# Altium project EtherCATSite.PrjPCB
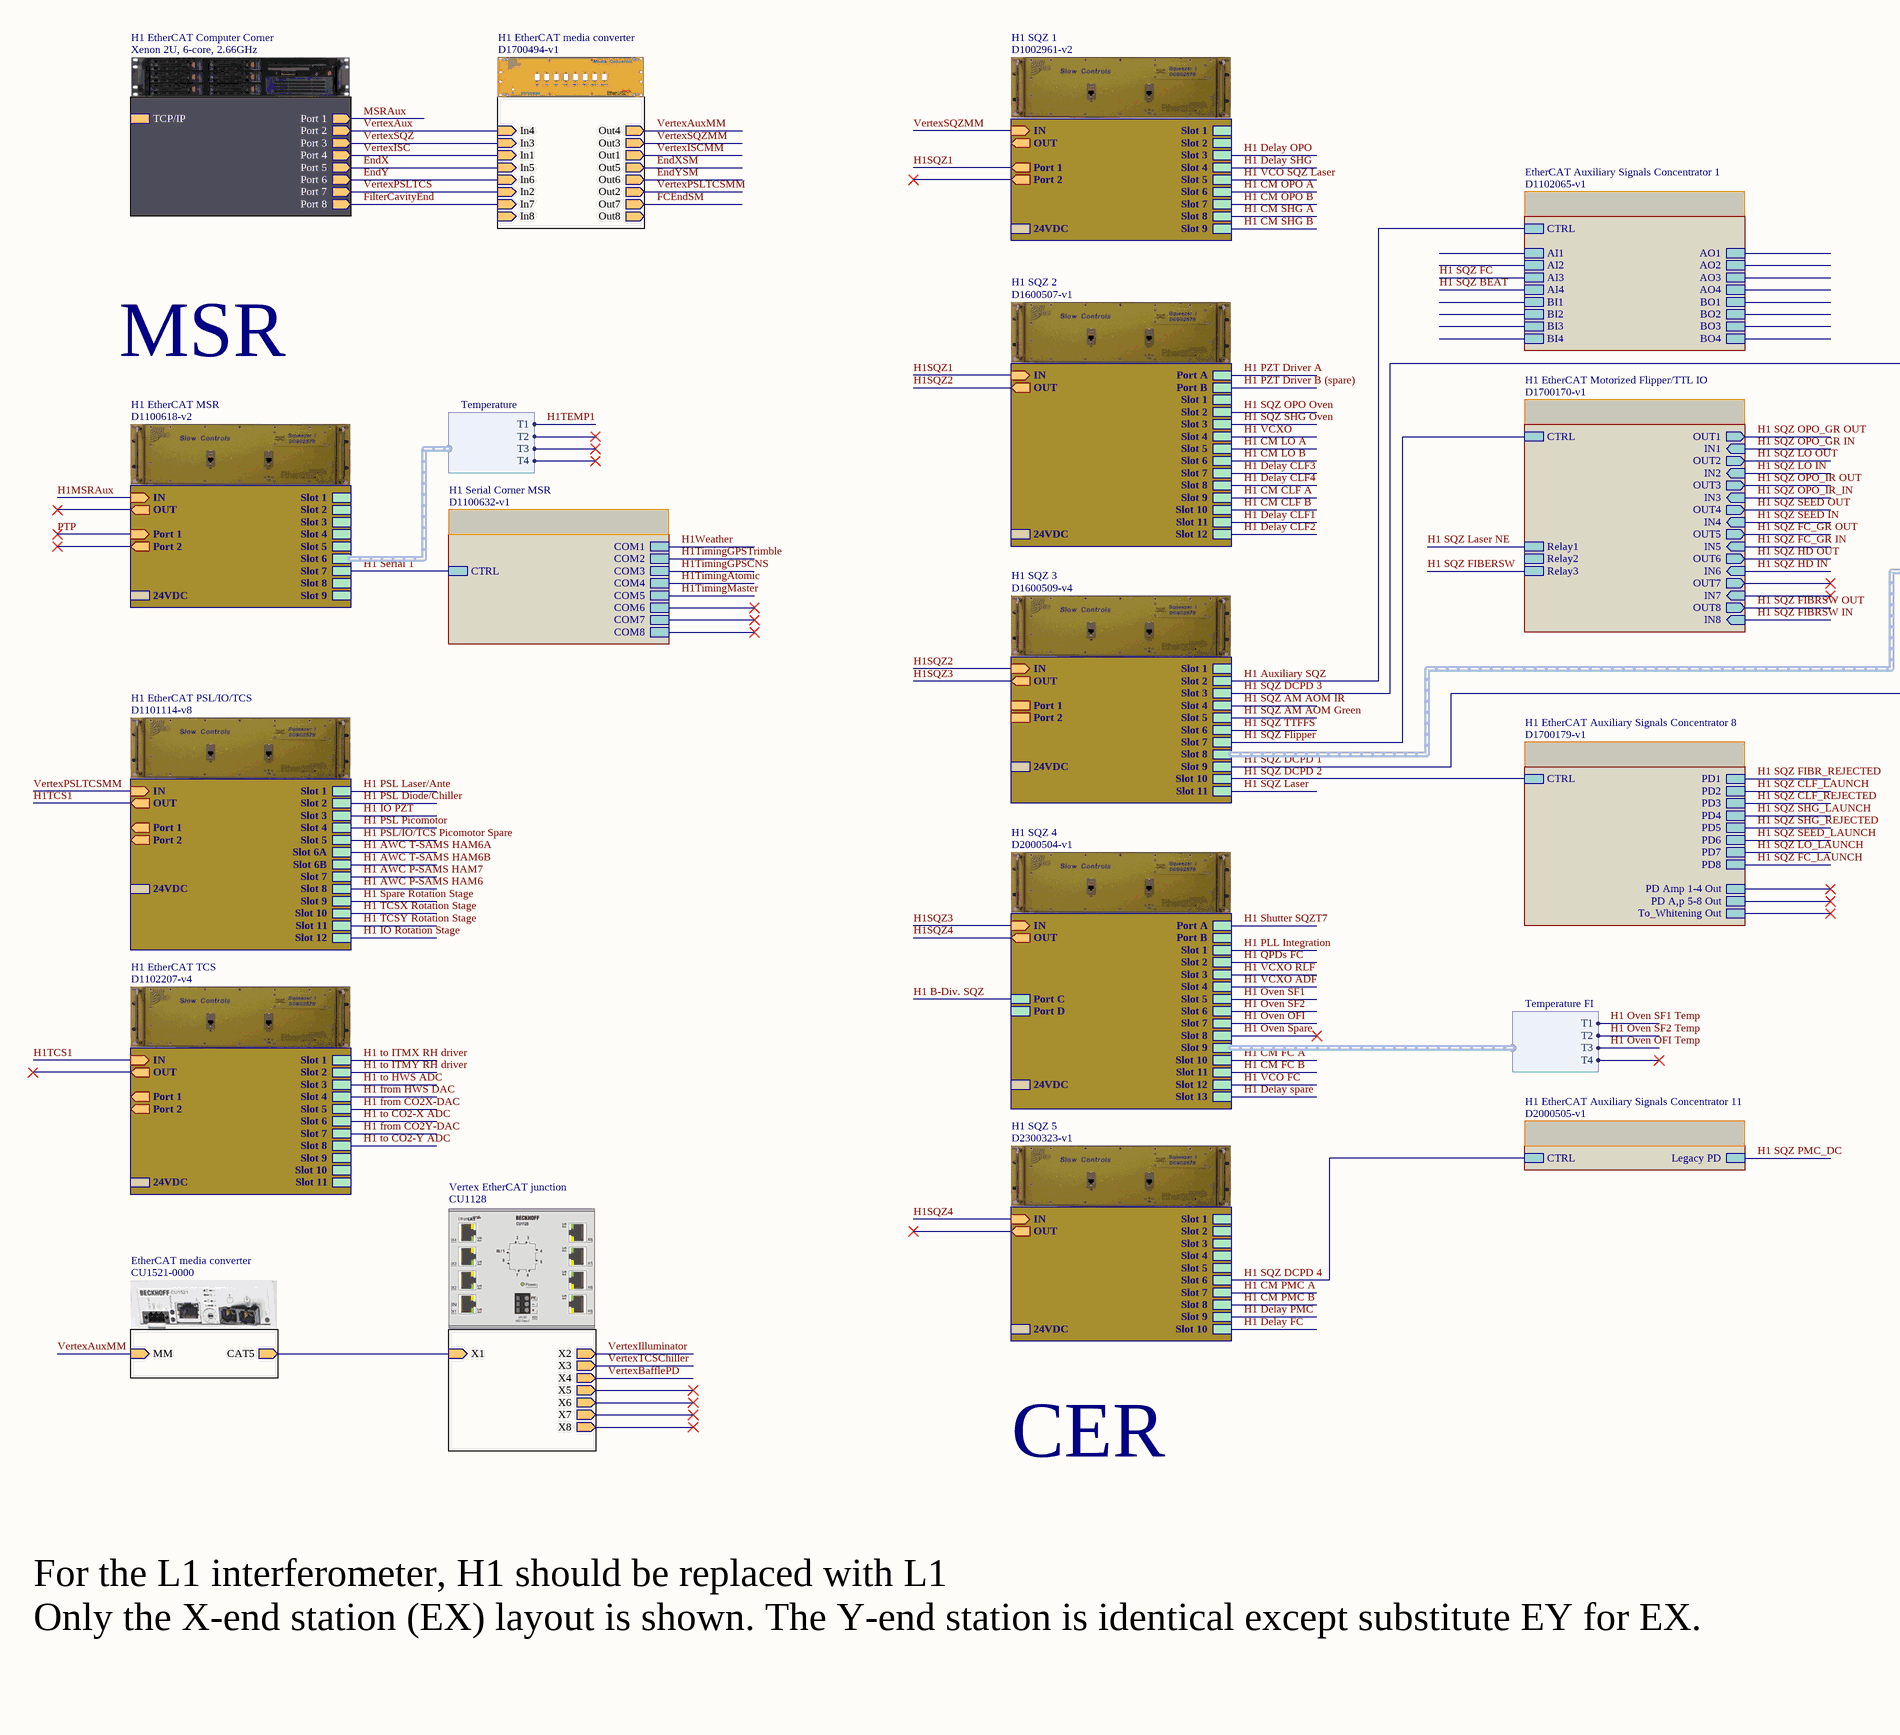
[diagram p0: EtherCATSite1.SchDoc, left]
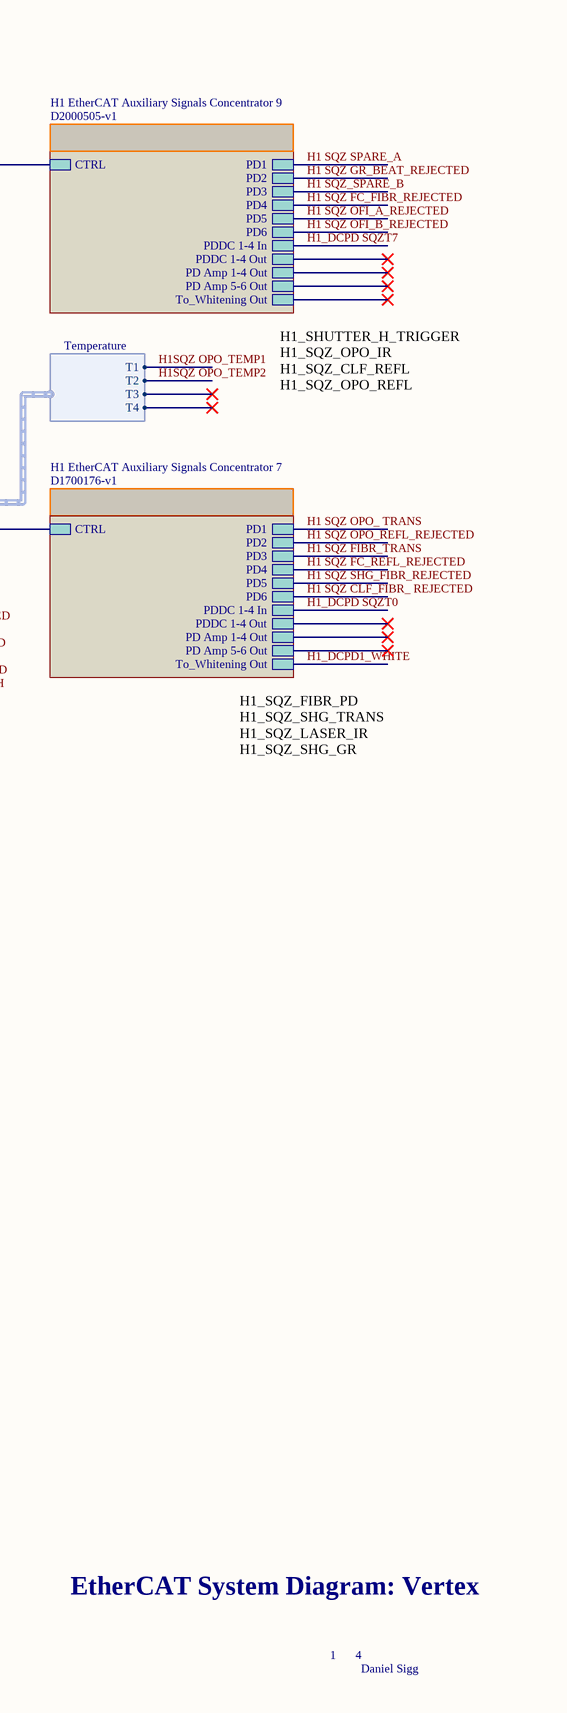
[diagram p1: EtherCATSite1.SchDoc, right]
Revision: 11; DCC: D1100683
4 sheets, 62 parts. Net scope: hierarchical (ports join the sheet entries above them; power ports are global).
Sheets:
  EtherCATSite1.SchDoc
  EtherCATSite2.SchDoc
  EtherCATSite3.SchDoc
  EtherCATSite4.SchDoc

## Sheet EtherCATSite1.SchDoc: D1100683
size C; Engineer: Daniel Sigg; PageSetup: Record=PageOptions¦CenterHorizontal=True¦CenterVertical=True¦PrintScale=0.72¦XCorrection=1.00¦YCorrection=1.00¦PrintKind=0¦BorderSize=5000000¦LeftOffset=0¦BottomOffset=0¦Orientation=2¦PaperLength=1000¦PaperWidth=1000¦Scale=100¦PaperSource=7¦PrintQuality=-3¦MediaType=1¦DitherType=10¦PrintScaleMode=1¦PaperKind=11 x 17¦PaperIndex=121

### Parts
(Parts that share a designator on the sheet are numbered #1, #2 ... from top to bottom, then left to right.)
EtherCAT_media_converter#1  Part Number: CU1521-0000  (hidden comment: EtherCAT media converter fibre optic)
H1_EtherCAT_Computer_Corner  Part Number: Xenon 2U, 6-core, 2.66GHz  (hidden comment: EtherCAT Computer)
H1_EtherCAT_media_converter  Part Number: D1700494-v1  (hidden comment: EtherCAT media converter)
H1_EtherCAT_MSR  Part Number: D1100618-v2  (hidden comment: EtherCAT Chassis)
H1_EtherCAT_PSL/IO/TCS  Part Number: D1101114-v8  (hidden comment: EtherCAT Chassis)
H1_EtherCAT_TCS  Part Number: D1102207-v4  (hidden comment: EtherCAT Chassis)
H1_Serial_Corner_MSR  Part Number: D1100632-v1  (hidden comment: EtherCAT Serial Concentrator)
H1_SQZ_1  Part Number: D1002961-v2  (hidden comment: EtherCAT Chassis)
H1_SQZ_2  Part Number: D1600507-v1  (hidden comment: EtherCAT Chassis)
H1_SQZ_3  Part Number: D1600509-v4  (hidden comment: EtherCAT Chassis)
H1_SQZ_4  Part Number: D2000504-v1  (hidden comment: EtherCAT Chassis)
H1_SQZ_5  Part Number: D2300323-v1  (hidden comment: EtherCAT Chassis)
U1  EtherCAT Auxiliary Signals Concentrator 1  Part Number: D1102065-v1
U2  H1 EtherCAT Auxiliary Signals Concentrator 9  Part Number: D2000505-v1
U3  H1 EtherCAT Motorized Flipper/TTL IO  Part Number: D1700170-v1
U4  H1 EtherCAT Auxiliary Signals Concentrator 7  Part Number: D1700176-v1
U5  H1 EtherCAT Auxiliary Signals Concentrator 8  Part Number: D1700179-v1
U6  H1 EtherCAT Auxiliary Signals Concentrator 11  Part Number: D2000505-v1
Vertex_EtherCAT_junction#1  EtherCAT junction  (value not drawn)

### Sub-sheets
EtherCAT4kmCorner = File Name (file not in this document): Slot 1, Slot 2, Slot 3, Slot 4, Slot 5, Slot 6 (harness Temperature), Slot 8, Slot 9, 24VDC, IN (in), OUT (out), Port 1 (in), Port 2 (out), Slot 7
EtherCAT4kmCorner = File Name (file not in this document): Slot 1, Slot 2, Slot 3, Slot 4, Slot 5, Slot 6, Slot 8, Slot 9, 24VDC, IN (in), OUT (out), Port 1 (out), Port 2 (out), Slot 7, Slot 10, Slot 11
EtherCAT4kmCorner = File Name (file not in this document): Slot 1, Slot 2, Slot 3, Slot 4, Slot 5, Slot 6A, 24VDC, IN (in), OUT (out), Port 1 (out), Port 2 (out), Slot 8, Slot 9, Slot 7, Slot 10, Slot 11, Slot 12, Slot 6B
EtherCAT4kmCorner = File Name (file not in this document): Slot 1, Slot 2, Slot 3, Slot 4, Slot 5, Slot 6, Slot 8, Slot 9, 24VDC, IN (in), OUT (out), Port 1 (out), Port 2 (out), Slot 7
EtherCAT4kmCorner = File Name (file not in this document): Port A, Slot 2, Slot 3, Slot 4, Slot 5, Slot 6, Slot 8, Slot 9, 24VDC, IN (in), OUT (out), Slot 7, Port B, Slot 10, Slot 11, Slot 12, Slot 1
EtherCAT4kmCorner = File Name (file not in this document): Slot 1, Slot 2, Slot 3, Slot 4, Slot 5, Slot 6, Slot 8 (harness Temperature), Slot 9, 24VDC, IN (in), OUT (out), Port 1, Port 2, Slot 7, Slot 10, Slot 11
EtherCAT4kmCorner = File Name (file not in this document): Port A, Slot 2, Slot 3, Slot 4, Slot 5, Slot 6, Slot 8, Slot 9 (harness Temperature FI), 24VDC, IN (in), OUT (out), Slot 7, Port B, Slot 10, Slot 11, Slot 12, Slot 1, Slot 13, Port C, Port D
EtherCAT4kmCorner = File Name (file not in this document): 24VDC, IN (in), OUT (out), Slot 2, Slot 3, Slot 4, Slot 5, Slot 6, Slot 8, Slot 9, Slot 7, Slot 10, Slot 1
H1 Serial Corner = File Name (file not in this document): CTRL, COM1, COM2, COM3, COM4, COM5, COM6, COM7, COM8
H1 Serial Corner = File Name (file not in this document): TCP/IP, Port 1 (out), Port 2 (out), Port 3 (out), Port 4 (out), Port 5 (out), Port 6 (out), Port 7 (out), Port 8 (out)
H1 Serial Corner = File Name (file not in this document): CTRL, PD1, PD2, PD3, PD4, PD Amp 1-4 Out, PD5, PD6, PD A,p 5-8 Out, To_Whitening Out, PD7, PD8
H1 Serial Corner = File Name (file not in this document): CTRL, PD1, PD2, PD3, PD4, PDDC 1-4 In, PDDC 1-4 Out, PD5, PD6, To_Whitening Out, PD Amp 1-4 Out, PD Amp 5-6 Out
H1 Serial Corner = File Name (file not in this document): CTRL, OUT1 (out), IN1 (in), OUT2 (out), OUT3 (out), OUT4 (out), OUT5 (out), OUT6 (out), OUT7 (out), OUT8 (out), IN2 (in), IN3 (in), IN4 (in), IN5 (in), IN6 (in), IN7 (in), IN8 (in), Relay1, Relay2, Relay3
H1 Serial Corner = File Name (file not in this document): In1 (in), Out1 (out), In2 (in), In3 (in), In4 (in), In5 (in), In6 (in), In7 (in), In8 (in), Out2 (out), Out3 (out), Out4 (out), Out5 (out), Out6 (out), Out7 (out), Out8 (out)
H1 Serial Corner = File Name (file not in this document): MM (in), CAT5 (out)
H1 Serial Corner = File Name (file not in this document): X2 (out), X1 (in), X3 (out), X4 (out), X5 (out), X6 (out), X7 (out), X8 (out)
H1 Serial Corner = File Name (file not in this document): CTRL, PD1, PD2, PD3, PD4, PDDC 1-4 In, PDDC 1-4 Out, PD5, PD6, To_Whitening Out, PD Amp 1-4 Out, PD Amp 5-6 Out
H1 Serial Corner = File Name (file not in this document): CTRL, AI1, AI2, AI3, AI4, AO1, AO2, AO3, AO4, BI1, BO1, BI2, BI3, BI4, BO2, BO3, BO4
H1 Serial Corner = File Name (file not in this document): CTRL, Legacy PD

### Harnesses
Temperature: T1, T2, T3, T4
Temperature FI: T1, T2, T3, T4

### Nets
EndX: sheet H1 Serial Corner/Port 5, sheet H1 Serial Corner/In5
EndY: sheet H1 Serial Corner/Port 6, sheet H1 Serial Corner/In6
FilterCavityEnd: sheet H1 Serial Corner/Port 8, sheet H1 Serial Corner/In7
H1 Auxiliary SQZ: sheet EtherCAT4kmCorner/Slot 2, sheet H1 Serial Corner/CTRL
H1 Serial 1: sheet EtherCAT4kmCorner/Slot 7, sheet H1 Serial Corner/CTRL
H1 SQZ DCPD 1: sheet H1 Serial Corner/CTRL, sheet EtherCAT4kmCorner/Slot 9
H1 SQZ DCPD 2: sheet H1 Serial Corner/CTRL, sheet EtherCAT4kmCorner/Slot 10
H1 SQZ DCPD 3: sheet EtherCAT4kmCorner/Slot 3, sheet H1 Serial Corner/CTRL
H1 SQZ DCPD 4: sheet EtherCAT4kmCorner/Slot 6, sheet H1 Serial Corner/CTRL
H1 SQZ Flipper: sheet H1 Serial Corner/CTRL, sheet EtherCAT4kmCorner/Slot 7
H1SQZ1: sheet EtherCAT4kmCorner/Port 1, sheet EtherCAT4kmCorner/IN
H1SQZ2: sheet EtherCAT4kmCorner/OUT, sheet EtherCAT4kmCorner/IN
H1SQZ3: sheet EtherCAT4kmCorner/OUT, sheet EtherCAT4kmCorner/IN
H1SQZ4: sheet EtherCAT4kmCorner/OUT, sheet EtherCAT4kmCorner/IN
H1TCS1: sheet EtherCAT4kmCorner/IN, sheet EtherCAT4kmCorner/OUT
VertexAux: sheet H1 Serial Corner/Port 2, sheet H1 Serial Corner/In4
VertexAuxMM: sheet H1 Serial Corner/Out4, sheet H1 Serial Corner/MM
VertexISC: sheet H1 Serial Corner/Port 4, sheet H1 Serial Corner/In1
VertexPSLTCS: sheet H1 Serial Corner/Port 7, sheet H1 Serial Corner/In2
VertexPSLTCSMM: sheet EtherCAT4kmCorner/IN, sheet H1 Serial Corner/Out2
VertexSQZ: sheet H1 Serial Corner/Port 3, sheet H1 Serial Corner/In3
VertexSQZMM: sheet EtherCAT4kmCorner/IN, sheet H1 Serial Corner/Out3
(unnamed): sheet H1 Serial Corner/CAT5, sheet H1 Serial Corner/X1

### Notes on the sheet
- MSR
- H1_SHUTTER_H_TRIGGER
  H1_SQZ_OPO_IR
  H1_SQZ_CLF_REFL
  H1_SQZ_OPO_REFL
- H1_SQZ_FIBR_PD
  H1_SQZ_SHG_TRANS
  H1_SQZ_LASER_IR
  H1_SQZ_SHG_GR
- CER
- For the L1 interferometer, H1 should be replaced with L1
  Only the X-end station (EX) layout is shown. The Y-end station is identical except substitute EY for EX.
- EtherCAT System Diagram: Vertex
- 1
- 4
- Daniel Sigg

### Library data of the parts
EtherCAT_media_converter#1 = CU1521small
H1_EtherCAT_Computer_Corner = EtherCATcomputer
H1_EtherCAT_media_converter = EtherCATMediaConverter
H1_EtherCAT_MSR H1_EtherCAT_PSL/IO/TCS H1_EtherCAT_TCS H1_SQZ_1-H1_SQZ_5 = EtherCATchassis
H1_Serial_Corner_MSR = EtherCATConcentratorSerial
U1-U6 = EtherCATConcentratorAux1: EtherCAT Auxiliary  Signals Concentrator 1
Vertex_EtherCAT_junction#1 = CU1128

## Sheet EtherCATSite2.SchDoc: D1100683
size C; Engineer: Daniel Sigg; PageSetup: Record=PageOptions¦CenterHorizontal=True¦CenterVertical=True¦PrintScale=1.18¦XCorrection=1.00¦YCorrection=1.00¦PrintKind=0¦BorderSize=5000000¦LeftOffset=0¦BottomOffset=0¦Orientation=2¦PaperLength=1000¦PaperWidth=1000¦Scale=100¦PaperSource=7¦PrintQuality=-4¦MediaType=1¦DitherType=10¦PaperKind=ARCH C¦PrintScaleMode=1
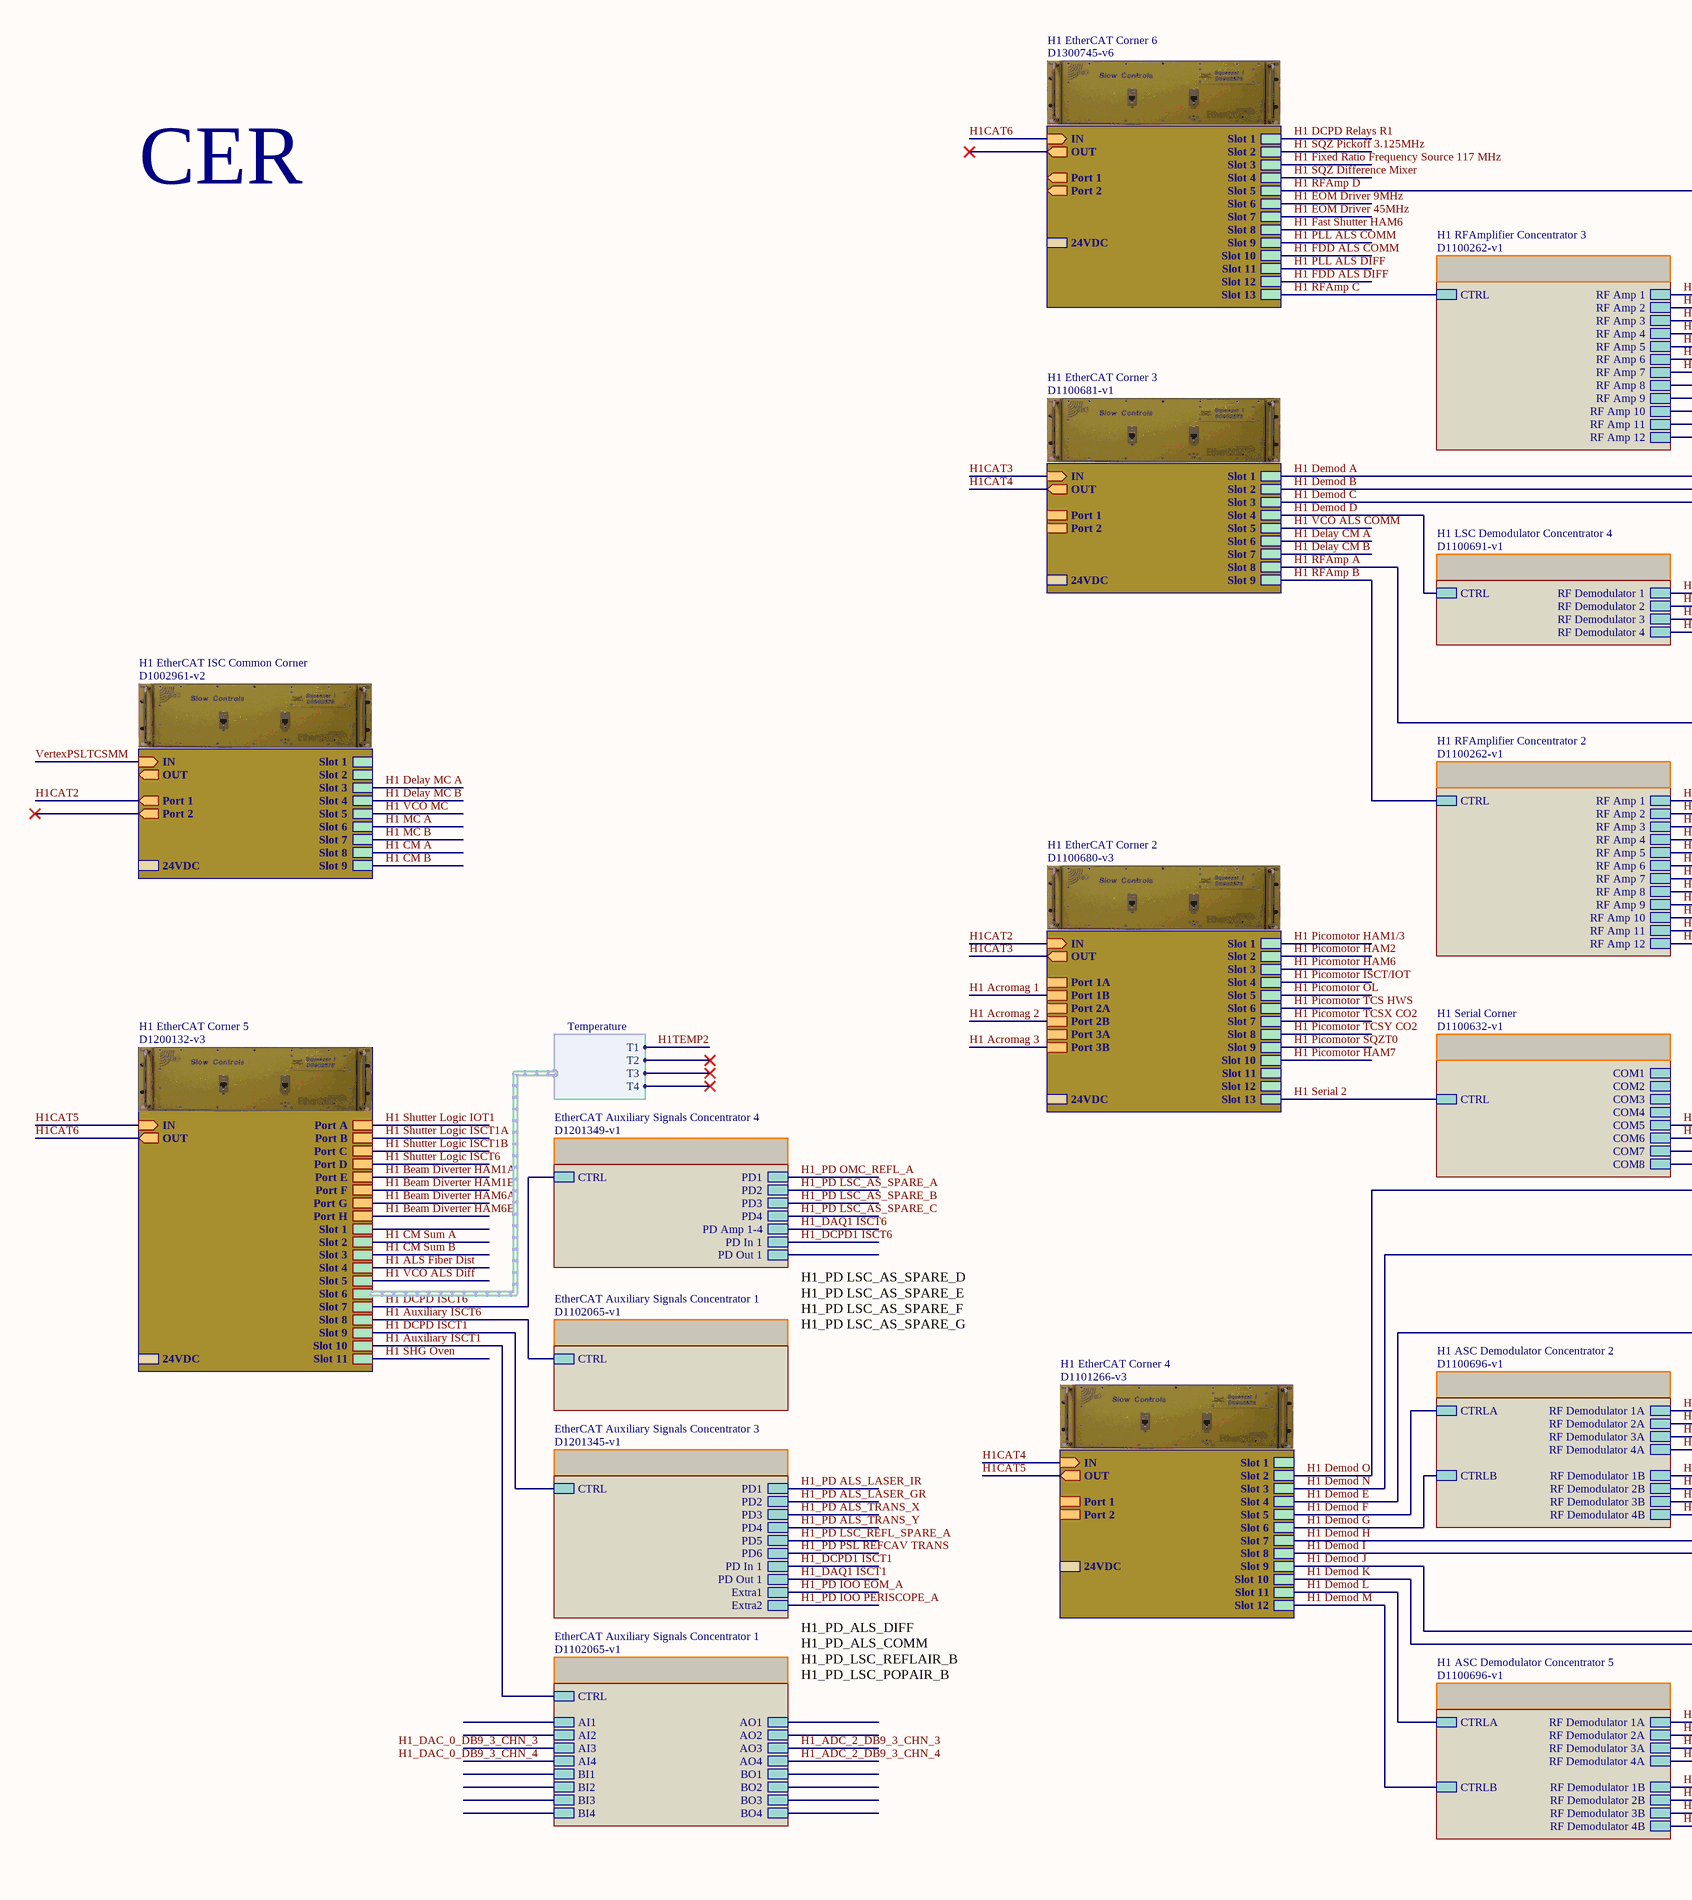
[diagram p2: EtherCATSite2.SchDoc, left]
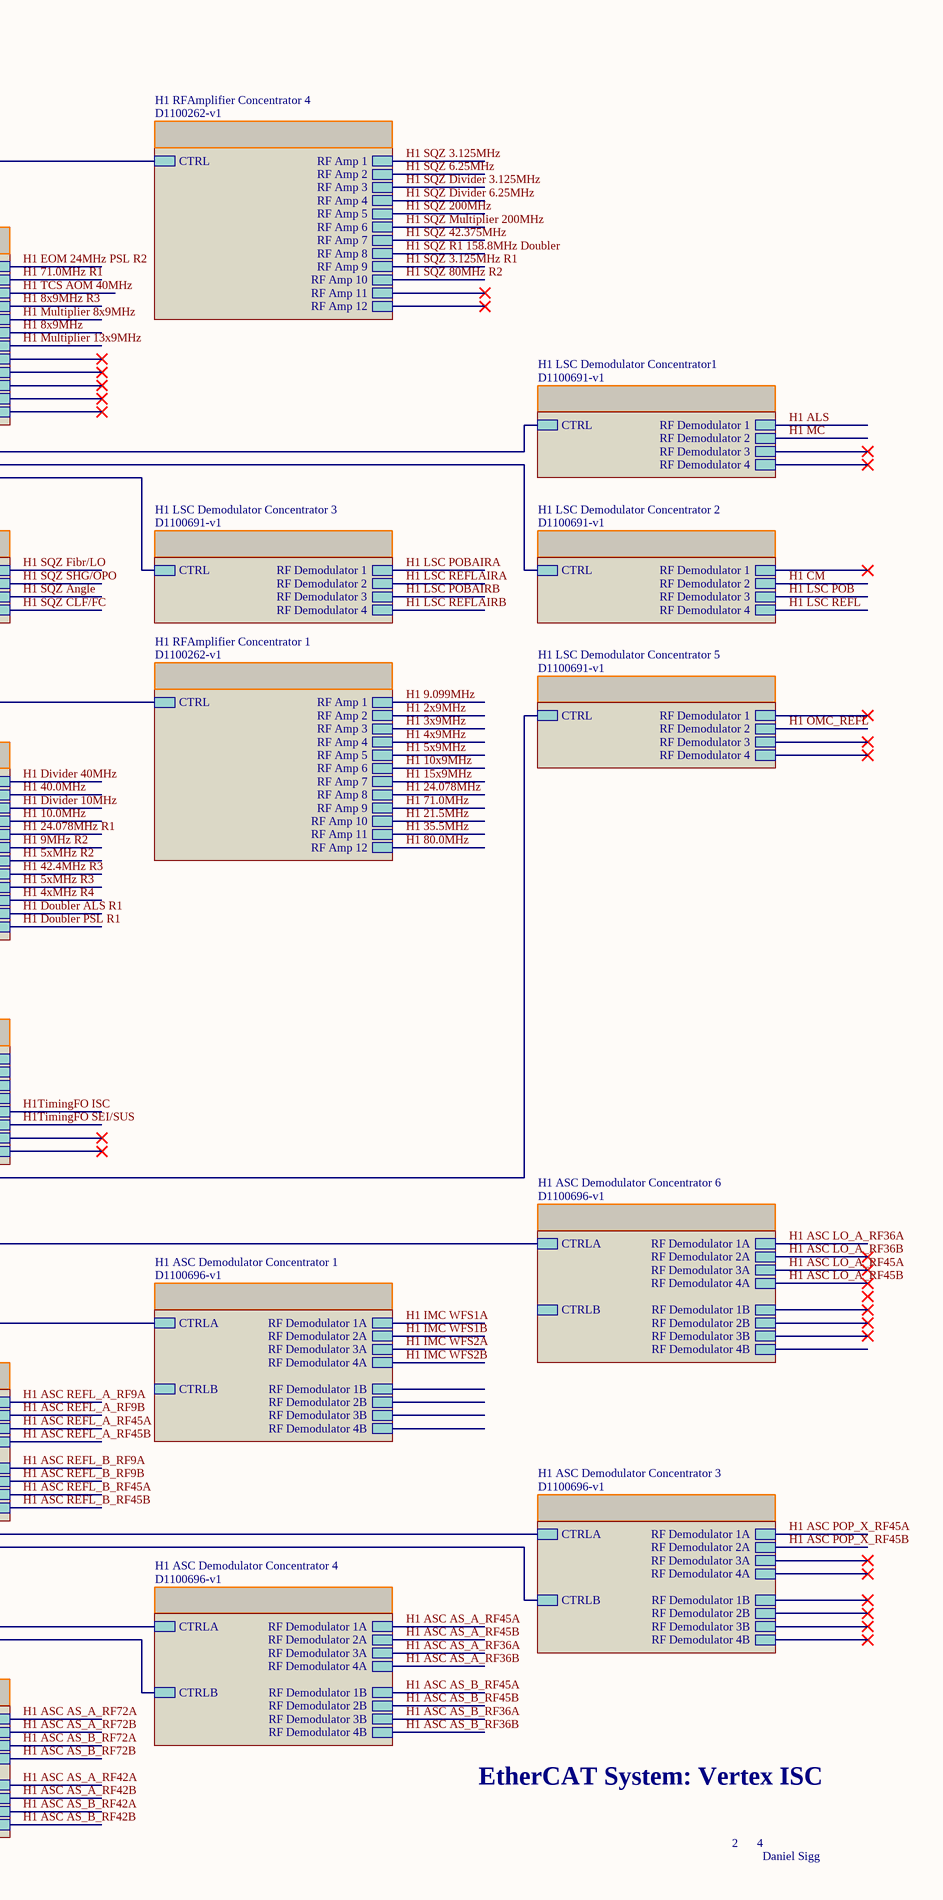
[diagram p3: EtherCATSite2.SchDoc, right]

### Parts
(Parts that share a designator on the sheet are numbered #1, #2 ... from top to bottom, then left to right.)
H1_ASC_Demodulator_Concentrator_1#1  Part Number: D1100696-v1  (hidden comment: EtherCAT Demod Concentrator)
H1_ASC_Demodulator_Concentrator_2  Part Number: D1100696-v1  (hidden comment: EtherCAT Demod Concentrator)
H1_ASC_Demodulator_Concentrator_3  Part Number: D1100696-v1  (hidden comment: EtherCAT Demod Concentrator)
H1_ASC_Demodulator_Concentrator_4  Part Number: D1100696-v1  (hidden comment: EtherCAT Demod Concentrator)
H1_ASC_Demodulator_Concentrator_5  Part Number: D1100696-v1  (hidden comment: EtherCAT Demod Concentrator)
H1_ASC_Demodulator_Concentrator_6  Part Number: D1100696-v1  (hidden comment: EtherCAT Demod Concentrator)
H1_EtherCAT_Corner_2  Part Number: D1100680-v3  (hidden comment: EtherCAT Chassis)
H1_EtherCAT_Corner_3  Part Number: D1100681-v1  (hidden comment: EtherCAT Chassis)
H1_EtherCAT_Corner_4  Part Number: D1101266-v3  (hidden comment: EtherCAT Chassis)
H1_EtherCAT_Corner_5  Part Number: D1200132-v3  (hidden comment: EtherCAT Chassis)
H1_EtherCAT_Corner_6  Part Number: D1300745-v6  (hidden comment: EtherCAT Chassis)
H1_EtherCAT_ISC_Common_Corner  Part Number: D1002961-v2  (hidden comment: EtherCAT Chassis)
H1_LSC_Demodulator_Concentrator1  Part Number: D1100691-v1  (hidden comment: EtherCAT Demod Concentrator)
H1_LSC_Demodulator_Concentrator_2  Part Number: D1100691-v1  (hidden comment: EtherCAT Demod Concentrator)
H1_LSC_Demodulator_Concentrator_3  Part Number: D1100691-v1  (hidden comment: EtherCAT Demod Concentrator)
H1_LSC_Demodulator_Concentrator_4  Part Number: D1100691-v1  (hidden comment: EtherCAT Demod Concentrator)
H1_LSC_Demodulator_Concentrator_5#1  Part Number: D1100691-v1  (hidden comment: EtherCAT Demod Concentrator)
H1_RFAmplifier_Concentrator_1  Part Number: D1100262-v1  (hidden comment: EtherCAT RF Amp Concentrator)
H1_RFAmplifier_Concentrator_2  Part Number: D1100262-v1  (hidden comment: EtherCAT RF Amp Concentrator)
H1_RFAmplifier_Concentrator_3#1  Part Number: D1100262-v1  (hidden comment: EtherCAT RF Amp Concentrator)
H1_RFAmplifier_Concentrator_4  Part Number: D1100262-v1  (hidden comment: EtherCAT RF Amp Concentrator)
H1_Serial_Corner  Part Number: D1100632-v1  (hidden comment: EtherCAT Serial Concentrator)
U7  EtherCAT Auxiliary Signals Concentrator 4  Part Number: D1201349-v1
U8  EtherCAT Auxiliary Signals Concentrator 1  Part Number: D1102065-v1
U9  EtherCAT Auxiliary Signals Concentrator 3  Part Number: D1201345-v1
U10  EtherCAT Auxiliary Signals Concentrator 1  Part Number: D1102065-v1

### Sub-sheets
EtherCAT4kmCorner = File Name (file not in this document): Slot 1, Slot 2, Slot 3, Slot 4, Slot 5, Slot 6, Slot 8, Slot 9, 24VDC, IN (in), OUT (out), Port 1 (out), Port 2 (out), Slot 7
EtherCAT4kmCorner = File Name (file not in this document): Slot 1, Slot 2, Slot 3, Slot 4, Slot 5, Slot 6, Slot 8, Slot 9, 24VDC, IN (in), OUT (out), Port 1, Port 2, Slot 7, Slot 10, Slot 11, Slot 12
EtherCAT4kmCorner = File Name (file not in this document): Slot 1, Slot 2, Slot 3, Slot 4, Slot 5, Slot 6, Slot 8, Slot 9, 24VDC, IN (in), OUT (out), Port 1, Port 2, Slot 7
EtherCAT4kmCorner = File Name (file not in this document): Slot 1, Slot 2, Slot 3, Slot 4, Slot 5, Slot 6, Slot 8, Slot 9, 24VDC, IN (in), OUT (out), Port 1A, Port 2A, Slot 7, Slot 10, Slot 11, Slot 12, Slot 13, Port 1B, Port 2B, Port 3A, Port 3B
EtherCAT4kmCorner = File Name (file not in this document): Slot 1, Slot 2, Slot 4, Slot 5, Slot 6 (harness Temperature), Slot 7, Slot 8, Slot 9, IN (in), OUT (out), 24VDC, Port A, Port B, Port C, Port D, Port E, Port F, Port G, Port H, Slot 10, Slot 3, Slot 11
EtherCAT4kmCorner = File Name (file not in this document): Slot 1, Slot 2, Slot 3, Slot 4, Slot 5, Slot 6, Slot 8, Slot 9, 24VDC, IN (in), OUT (out), Port 1 (out), Port 2 (out), Slot 7, Slot 10, Slot 11, Slot 12, Slot 13
H1 Serial Corner = File Name (file not in this document): CTRL, RF Amp 1, RF Amp 2, RF Amp 3, RF Amp 4, RF Amp 5, RF Amp 6, RF Amp 7, RF Amp 8, RF Amp 9, RF Amp 10, RF Amp 11, RF Amp 12
H1 Serial Corner = File Name (file not in this document): CTRL, RF Amp 1, RF Amp 2, RF Amp 3, RF Amp 4, RF Amp 5, RF Amp 6, RF Amp 7, RF Amp 8, RF Amp 9, RF Amp 10, RF Amp 11, RF Amp 12
H1 Serial Corner = File Name (file not in this document): CTRL, COM1, COM2, COM3, COM4, COM5, COM6, COM7, COM8
H1 Serial Corner = File Name (file not in this document): CTRL, RF Demodulator 1, RF Demodulator 2, RF Demodulator 3, RF Demodulator 4
H1 Serial Corner = File Name (file not in this document): CTRLA, RF Demodulator 1A, RF Demodulator 2A, RF Demodulator 3A, RF Demodulator 4A, CTRLB, RF Demodulator 1B, RF Demodulator 2B, RF Demodulator 3B, RF Demodulator 4B
H1 Serial Corner = File Name (file not in this document): CTRL, RF Demodulator 1, RF Demodulator 2, RF Demodulator 3, RF Demodulator 4
H1 Serial Corner = File Name (file not in this document): CTRL, RF Demodulator 1, RF Demodulator 2, RF Demodulator 3, RF Demodulator 4
H1 Serial Corner = File Name (file not in this document): CTRL, RF Demodulator 1, RF Demodulator 2, RF Demodulator 3, RF Demodulator 4
H1 Serial Corner = File Name (file not in this document): CTRLA, RF Demodulator 1A, RF Demodulator 2A, RF Demodulator 3A, RF Demodulator 4A, CTRLB, RF Demodulator 1B, RF Demodulator 2B, RF Demodulator 3B, RF Demodulator 4B
H1 Serial Corner = File Name (file not in this document): CTRLA, RF Demodulator 1A, RF Demodulator 2A, RF Demodulator 3A, RF Demodulator 4A, CTRLB, RF Demodulator 1B, RF Demodulator 2B, RF Demodulator 3B, RF Demodulator 4B
H1 Serial Corner = File Name (file not in this document): CTRLA, RF Demodulator 1A, RF Demodulator 2A, RF Demodulator 3A, RF Demodulator 4A, CTRLB, RF Demodulator 1B, RF Demodulator 2B, RF Demodulator 3B, RF Demodulator 4B
H1 Serial Corner = File Name (file not in this document): CTRLA, RF Demodulator 1A, RF Demodulator 2A, RF Demodulator 3A, RF Demodulator 4A, CTRLB, RF Demodulator 1B, RF Demodulator 2B, RF Demodulator 3B, RF Demodulator 4B
H1 Serial Corner = File Name (file not in this document): CTRL, AI1, AI2, AI3, AI4, AO1, AO2, AO3, AO4, BI1, BO1, BI2, BI3, BI4, BO2, BO3, BO4
H1 Serial Corner = File Name (file not in this document): CTRL
H1 Serial Corner = File Name (file not in this document): CTRL, PD1, PD2, PD3, PD4, PD In 1, PD Out 1, PD Amp 1-4
H1 Serial Corner = File Name (file not in this document): CTRL, PD1, PD2, PD3, PD4, PD In 1, PD Out 1, PD5, PD6, Extra1, Extra2
H1 Serial Corner = File Name (file not in this document): CTRL, RF Amp 1, RF Amp 2, RF Amp 3, RF Amp 4, RF Amp 5, RF Amp 6, RF Amp 7, RF Amp 8, RF Amp 9, RF Amp 10, RF Amp 11, RF Amp 12
H1 Serial Corner = File Name (file not in this document): CTRL, RF Amp 1, RF Amp 2, RF Amp 3, RF Amp 4, RF Amp 5, RF Amp 6, RF Amp 7, RF Amp 8, RF Amp 9, RF Amp 10, RF Amp 11, RF Amp 12
H1 Serial Corner = File Name (file not in this document): CTRLA, RF Demodulator 1A, RF Demodulator 2A, RF Demodulator 3A, RF Demodulator 4A, CTRLB, RF Demodulator 1B, RF Demodulator 2B, RF Demodulator 3B, RF Demodulator 4B
H1 Serial Corner = File Name (file not in this document): CTRL, RF Demodulator 1, RF Demodulator 2, RF Demodulator 3, RF Demodulator 4

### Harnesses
Temperature: T1, T2, T3, T4

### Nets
H1 Auxiliary ISCT1: sheet EtherCAT4kmCorner/Slot 10, sheet H1 Serial Corner/CTRL
H1 Auxiliary ISCT6: sheet EtherCAT4kmCorner/Slot 8, sheet H1 Serial Corner/CTRL
H1 DCPD ISCT1: sheet EtherCAT4kmCorner/Slot 9, sheet H1 Serial Corner/CTRL
H1 DCPD ISCT6: sheet EtherCAT4kmCorner/Slot 7, sheet H1 Serial Corner/CTRL
H1 Demod A: sheet EtherCAT4kmCorner/Slot 1, sheet H1 Serial Corner/CTRL
H1 Demod B: sheet EtherCAT4kmCorner/Slot 2, sheet H1 Serial Corner/CTRL
H1 Demod C: sheet EtherCAT4kmCorner/Slot 3, sheet H1 Serial Corner/CTRL
H1 Demod D: sheet EtherCAT4kmCorner/Slot 4, sheet H1 Serial Corner/CTRL
H1 Demod E: sheet EtherCAT4kmCorner/Slot 4, sheet H1 Serial Corner/CTRLA
H1 Demod F: sheet EtherCAT4kmCorner/Slot 5, sheet H1 Serial Corner/CTRLA
H1 Demod G: sheet EtherCAT4kmCorner/Slot 6, sheet H1 Serial Corner/CTRLB
H1 Demod H: sheet EtherCAT4kmCorner/Slot 7, sheet H1 Serial Corner/CTRLA
H1 Demod I: sheet EtherCAT4kmCorner/Slot 8, sheet H1 Serial Corner/CTRLB
H1 Demod J: sheet EtherCAT4kmCorner/Slot 9, sheet H1 Serial Corner/CTRLA
H1 Demod K: sheet EtherCAT4kmCorner/Slot 10, sheet H1 Serial Corner/CTRLB
H1 Demod L: sheet EtherCAT4kmCorner/Slot 11, sheet H1 Serial Corner/CTRLA
H1 Demod M: sheet EtherCAT4kmCorner/Slot 12, sheet H1 Serial Corner/CTRLB
H1 Demod N: sheet EtherCAT4kmCorner/Slot 3, sheet H1 Serial Corner/CTRLA
H1 Demod O: sheet EtherCAT4kmCorner/Slot 2, sheet H1 Serial Corner/CTRL
H1 RFAmp A: sheet EtherCAT4kmCorner/Slot 8, sheet H1 Serial Corner/CTRL
H1 RFAmp B: sheet EtherCAT4kmCorner/Slot 9, sheet H1 Serial Corner/CTRL
H1 RFAmp C: sheet H1 Serial Corner/CTRL, sheet EtherCAT4kmCorner/Slot 13
H1 RFAmp D: sheet EtherCAT4kmCorner/Slot 5, sheet H1 Serial Corner/CTRL
H1 Serial 2: sheet EtherCAT4kmCorner/Slot 13, sheet H1 Serial Corner/CTRL
H1CAT2: sheet EtherCAT4kmCorner/Port 1, sheet EtherCAT4kmCorner/IN
H1CAT3: sheet EtherCAT4kmCorner/IN, sheet EtherCAT4kmCorner/OUT
H1CAT4: sheet EtherCAT4kmCorner/IN, sheet EtherCAT4kmCorner/OUT
H1CAT5: sheet EtherCAT4kmCorner/OUT, sheet EtherCAT4kmCorner/IN
H1CAT6: sheet EtherCAT4kmCorner/OUT, sheet EtherCAT4kmCorner/IN

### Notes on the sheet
- CER
- H1_PD LSC_AS_SPARE_D
  H1_PD LSC_AS_SPARE_E
  H1_PD LSC_AS_SPARE_F
  H1_PD LSC_AS_SPARE_G
- H1_PD_ALS_DIFF
  H1_PD_ALS_COMM
  H1_PD_LSC_REFLAIR_B
  H1_PD_LSC_POPAIR_B
- EtherCAT System: Vertex ISC
- 2
- 4
- Daniel Sigg
- Labels drawn without touching a wire or pin: H1_DAC_0_DB9_3_CHN_3, H1_DAC_0_DB9_3_CHN_4

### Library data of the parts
H1_ASC_Demodulator_Concentrator_1#1 H1_ASC_Demodulator_Concentrator_2-H1_ASC_Demodulator_Concentrator_6 H1_LSC_Demodulator_Concentrator1 H1_LSC_Demodulator_Concentrator_2-H1_LSC_Demodulator_Concentrator_4 H1_LSC_Demodulator_Concentrator_5#1 = EtherCATConcentratorDemod
H1_EtherCAT_Corner_2-H1_EtherCAT_Corner_6 H1_EtherCAT_ISC_Common_Corner = EtherCATchassis
H1_RFAmplifier_Concentrator_1 H1_RFAmplifier_Concentrator_2 H1_RFAmplifier_Concentrator_3#1 H1_RFAmplifier_Concentrator_4 = EtherCATConcentratorRFAmp: EtherCAT RF Amplifier Concentrator
H1_Serial_Corner = EtherCATConcentratorSerial
U7-U10 = EtherCATConcentratorAux1: as U1 on sheet EtherCATSite1

## Sheet EtherCATSite3.SchDoc
size C
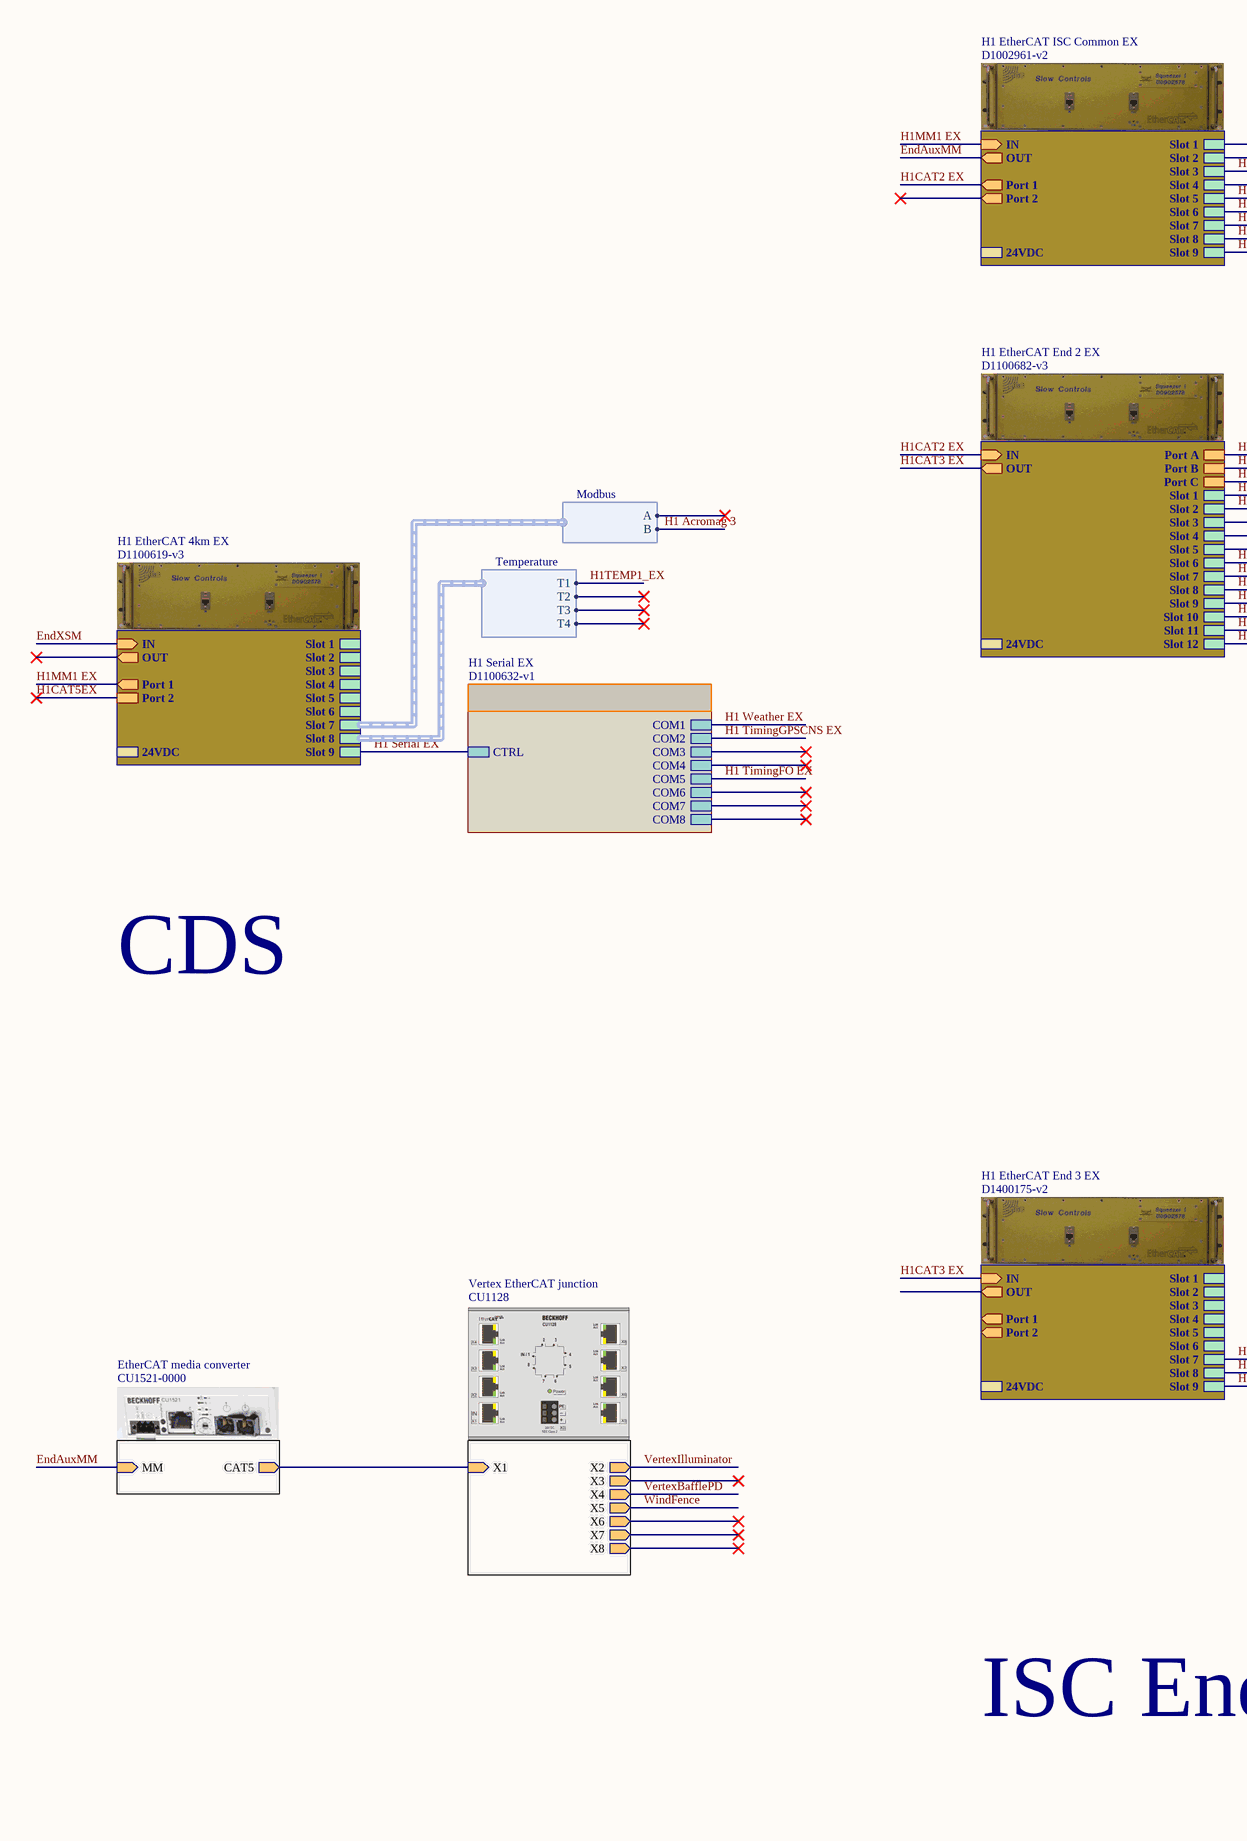
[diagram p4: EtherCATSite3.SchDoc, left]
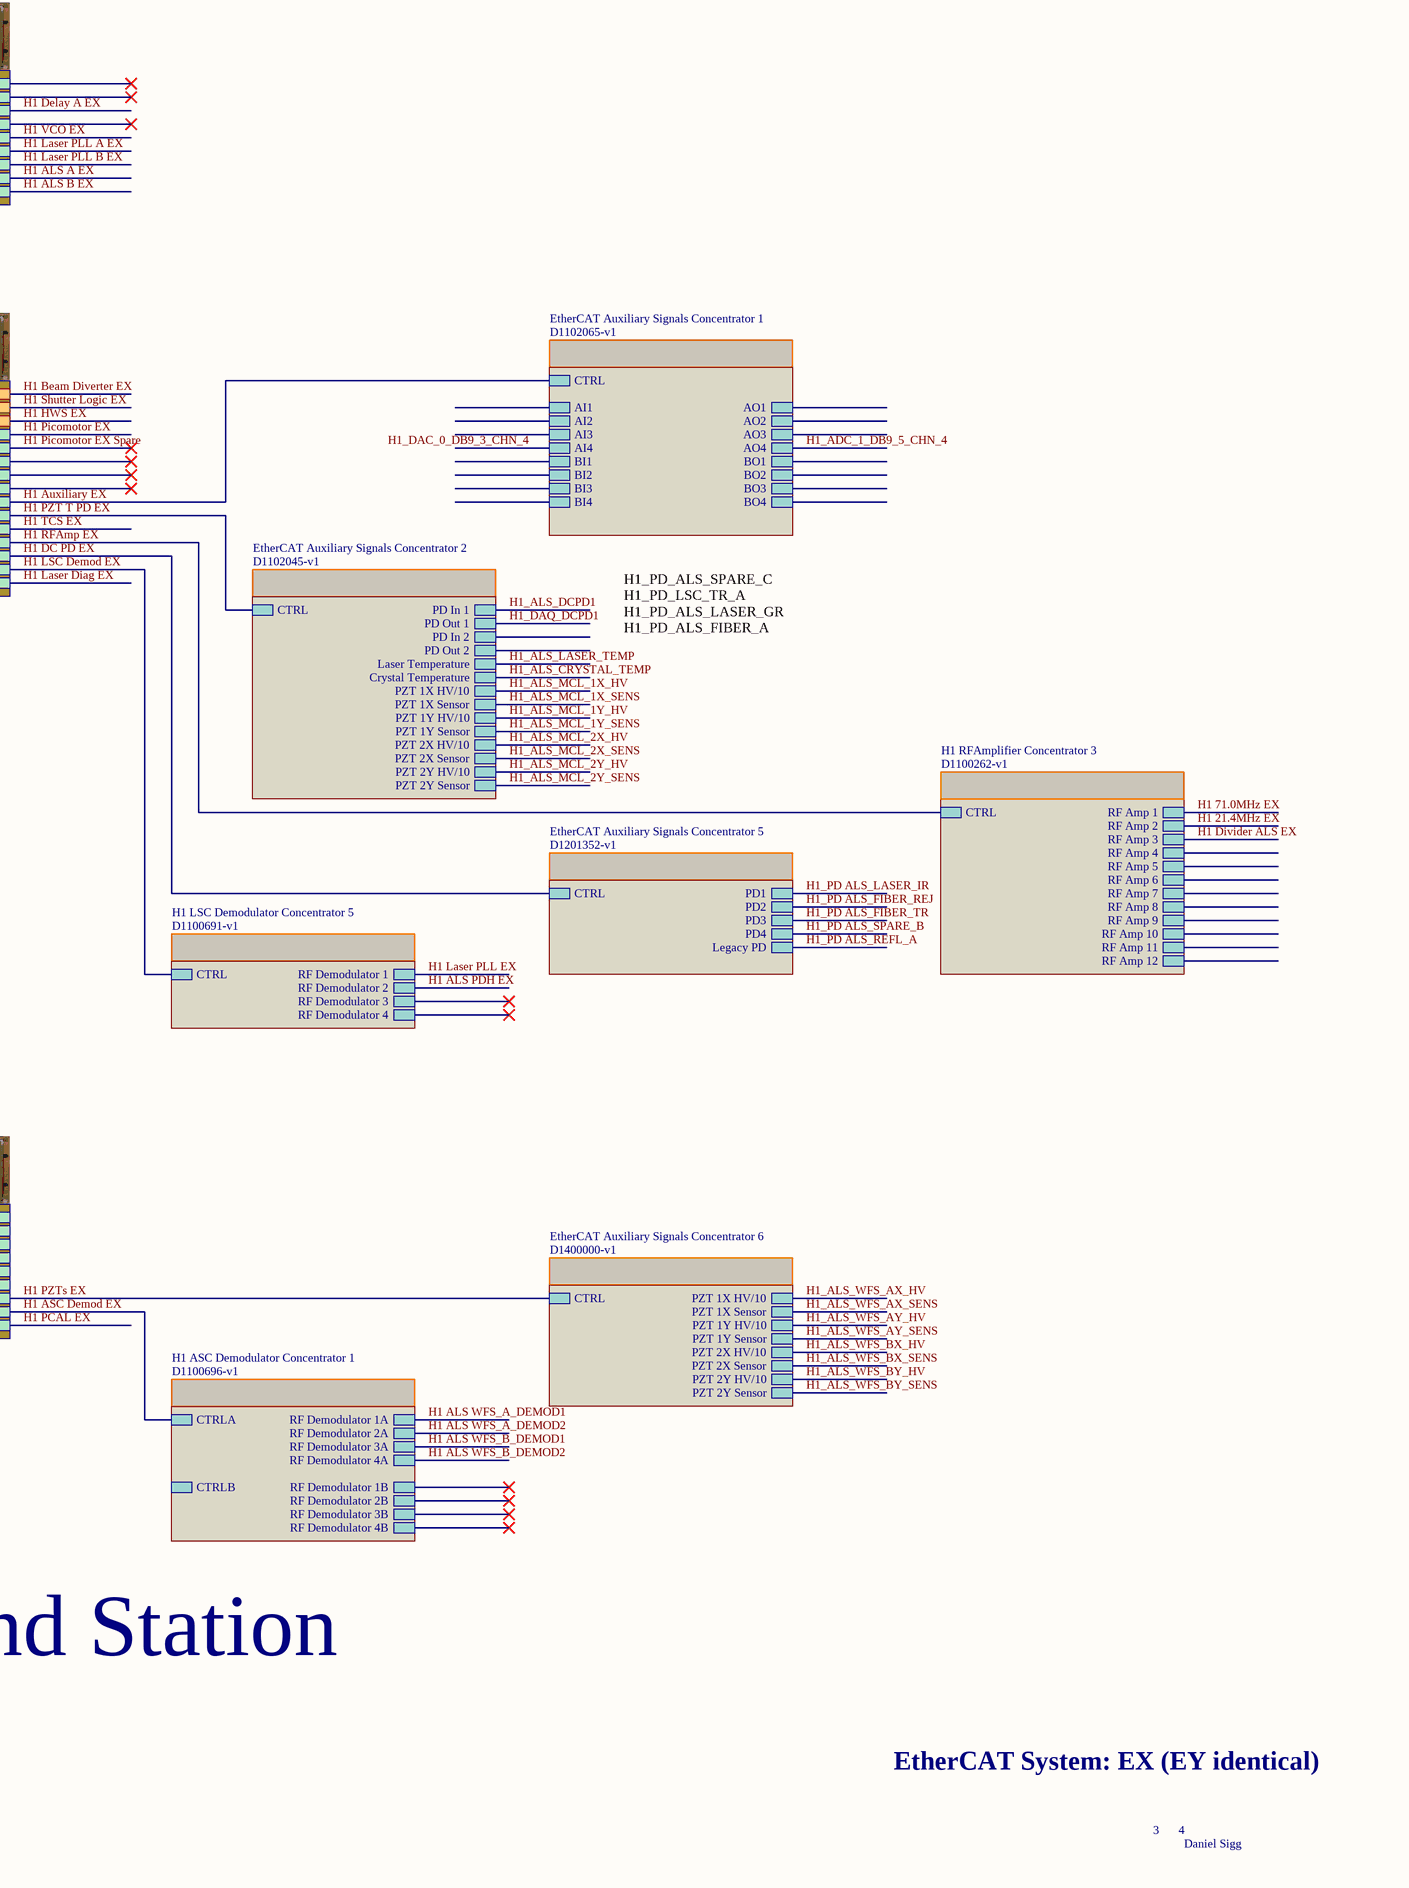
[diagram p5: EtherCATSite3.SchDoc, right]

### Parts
(Parts that share a designator on the sheet are numbered #1, #2 ... from top to bottom, then left to right.)
EtherCAT_media_converter#2  Part Number: CU1521-0000  (hidden comment: EtherCAT media converter fibre optic)
H1_ASC_Demodulator_Concentrator_1#2  Part Number: D1100696-v1  (hidden comment: EtherCAT Demod Concentrator)
H1_EtherCAT_4km_EX  Part Number: D1100619-v3  (hidden comment: EtherCAT Chassis)
H1_EtherCAT_End_2_EX  Part Number: D1100682-v3  (hidden comment: EtherCAT Chassis)
H1_EtherCAT_End_3_EX  Part Number: D1400175-v2  (hidden comment: EtherCAT Chassis)
H1_EtherCAT_ISC_Common_EX  Part Number: D1002961-v2  (hidden comment: EtherCAT Chassis)
H1_LSC_Demodulator_Concentrator_5#2  Part Number: D1100691-v1  (hidden comment: EtherCAT Demod Concentrator)
H1_RFAmplifier_Concentrator_3#2  Part Number: D1100262-v1  (hidden comment: EtherCAT RF Amp Concentrator)
H1_Serial_EX  Part Number: D1100632-v1  (hidden comment: EtherCAT Serial Concentrator)
U11  EtherCAT Auxiliary Signals Concentrator 1  Part Number: D1102065-v1
U12  EtherCAT Auxiliary Signals Concentrator 2  Part Number: D1102045-v1
U13  EtherCAT Auxiliary Signals Concentrator 5  Part Number: D1201352-v1
U14  EtherCAT Auxiliary Signals Concentrator 6  Part Number: D1400000-v1
Vertex_EtherCAT_junction#2  EtherCAT junction  (value not drawn)

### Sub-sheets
EtherCAT4kmCorner = File Name (file not in this document): Slot 1, Slot 2, Slot 3, Slot 4, Slot 5, Slot 6, Slot 8 (harness Temperature), Slot 9, 24VDC, IN (in), OUT (out), Port 1 (out), Port 2, Slot 7 (harness Modbus)
EtherCAT4kmCorner = File Name (file not in this document): Slot 1, Slot 2, Slot 3, Slot 4, Slot 5, Slot 6, Slot 8, Slot 9, 24VDC, IN (in), OUT (out), Port 1 (out), Port 2 (out), Slot 7
EtherCAT4kmCorner = File Name (file not in this document): Slot 1, Slot 2, Slot 3, Slot 4, Slot 5, Slot 6, Slot 8, Slot 9, 24VDC, IN (in), OUT (out), Port A, Port B, Slot 7, Slot 10, Slot 11, Slot 12, Port C
EtherCAT4kmCorner = File Name (file not in this document): Slot 1, Slot 2, Slot 3, Slot 4, Slot 5, Slot 6, Slot 8, Slot 9, 24VDC, IN (in), OUT (out), Port 1 (out), Port 2 (out), Slot 7
H1 Serial Corner = File Name (file not in this document): CTRL, COM1, COM2, COM3, COM4, COM5, COM6, COM7, COM8
H1 Serial Corner = File Name (file not in this document): CTRL, RF Amp 1, RF Amp 2, RF Amp 3, RF Amp 4, RF Amp 5, RF Amp 6, RF Amp 7, RF Amp 8, RF Amp 9, RF Amp 10, RF Amp 11, RF Amp 12
H1 Serial Corner = File Name (file not in this document): CTRL, RF Demodulator 1, RF Demodulator 2, RF Demodulator 3, RF Demodulator 4
H1 Serial Corner = File Name (file not in this document): CTRL, PD In 1, PD Out 1, PD In 2, PD Out 2, Laser Temperature, Crystal Temperature, PZT 1X HV/10, PZT 1X Sensor, PZT 1Y HV/10, PZT 1Y Sensor, PZT 2X HV/10, PZT 2X Sensor, PZT 2Y HV/10, PZT 2Y Sensor
H1 Serial Corner = File Name (file not in this document): CTRL, AI1, AI2, AI3, AI4, AO1, AO2, AO3, AO4, BI1, BO1, BI2, BI3, BI4, BO2, BO3, BO4
H1 Serial Corner = File Name (file not in this document): CTRL, PD1, PD2, PD3, PD4, Legacy PD
H1 Serial Corner = File Name (file not in this document): CTRLA, RF Demodulator 1A, RF Demodulator 2A, RF Demodulator 3A, RF Demodulator 4A, CTRLB, RF Demodulator 1B, RF Demodulator 2B, RF Demodulator 3B, RF Demodulator 4B
H1 Serial Corner = File Name (file not in this document): CTRL, PZT 1X HV/10, PZT 1X Sensor, PZT 1Y HV/10, PZT 1Y Sensor, PZT 2X HV/10, PZT 2X Sensor, PZT 2Y HV/10, PZT 2Y Sensor
H1 Serial Corner = File Name (file not in this document): MM (in), CAT5 (out)
H1 Serial Corner = File Name (file not in this document): X2 (out), X1 (in), X3 (out), X4 (out), X5 (out), X6 (out), X7 (out), X8 (out)

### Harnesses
Temperature: T1, T2, T3, T4
Modbus: A, B

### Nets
EndAuxMM: sheet EtherCAT4kmCorner/OUT, sheet H1 Serial Corner/MM
H1 ASC Demod EX: sheet EtherCAT4kmCorner/Slot 8, sheet H1 Serial Corner/CTRLA
H1 Auxiliary EX: sheet EtherCAT4kmCorner/Slot 6, sheet H1 Serial Corner/CTRL
H1 DC PD EX: sheet EtherCAT4kmCorner/Slot 10, sheet H1 Serial Corner/CTRL
H1 LSC Demod EX: sheet EtherCAT4kmCorner/Slot 11, sheet H1 Serial Corner/CTRL
H1 PZT T PD EX: sheet EtherCAT4kmCorner/Slot 7, sheet H1 Serial Corner/CTRL
H1 PZTs EX: sheet EtherCAT4kmCorner/Slot 7, sheet H1 Serial Corner/CTRL
H1 RFAmp EX: sheet EtherCAT4kmCorner/Slot 9, sheet H1 Serial Corner/CTRL
H1 Serial EX: sheet EtherCAT4kmCorner/Slot 9, sheet H1 Serial Corner/CTRL
H1CAT2 EX: sheet EtherCAT4kmCorner/Port 1, sheet EtherCAT4kmCorner/IN
H1CAT3 EX: sheet EtherCAT4kmCorner/OUT, sheet EtherCAT4kmCorner/IN
H1MM1 EX: sheet EtherCAT4kmCorner/Port 1, sheet EtherCAT4kmCorner/IN
(unnamed): sheet H1 Serial Corner/CAT5, sheet H1 Serial Corner/X1

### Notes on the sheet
- H1_PD_ALS_SPARE_C
  H1_PD_LSC_TR_A
  H1_PD_ALS_LASER_GR
  H1_PD_ALS_FIBER_A
- CDS
- ISC End Station
- EtherCAT System: EX (EY identical)
- 3
- 4
- Daniel Sigg
- Labels drawn without touching a wire or pin: H1_DAC_0_DB9_3_CHN_4

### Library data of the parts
EtherCAT_media_converter#2 = CU1521small
H1_ASC_Demodulator_Concentrator_1#2 H1_LSC_Demodulator_Concentrator_5#2 = EtherCATConcentratorDemod
H1_EtherCAT_4km_EX H1_EtherCAT_End_2_EX H1_EtherCAT_End_3_EX H1_EtherCAT_ISC_Common_EX = EtherCATchassis
H1_RFAmplifier_Concentrator_3#2 = EtherCATConcentratorRFAmp: EtherCAT RF Amplifier Concentrator
H1_Serial_EX = EtherCATConcentratorSerial
U11 U13 = EtherCATConcentratorAux1: as U1 on sheet EtherCATSite1
U12 U14 = EtherCATConcentratorAux2: EtherCAT Auxiliary  Signals Concentrator 2
Vertex_EtherCAT_junction#2 = CU1128

## Sheet EtherCATSite4.SchDoc
size C
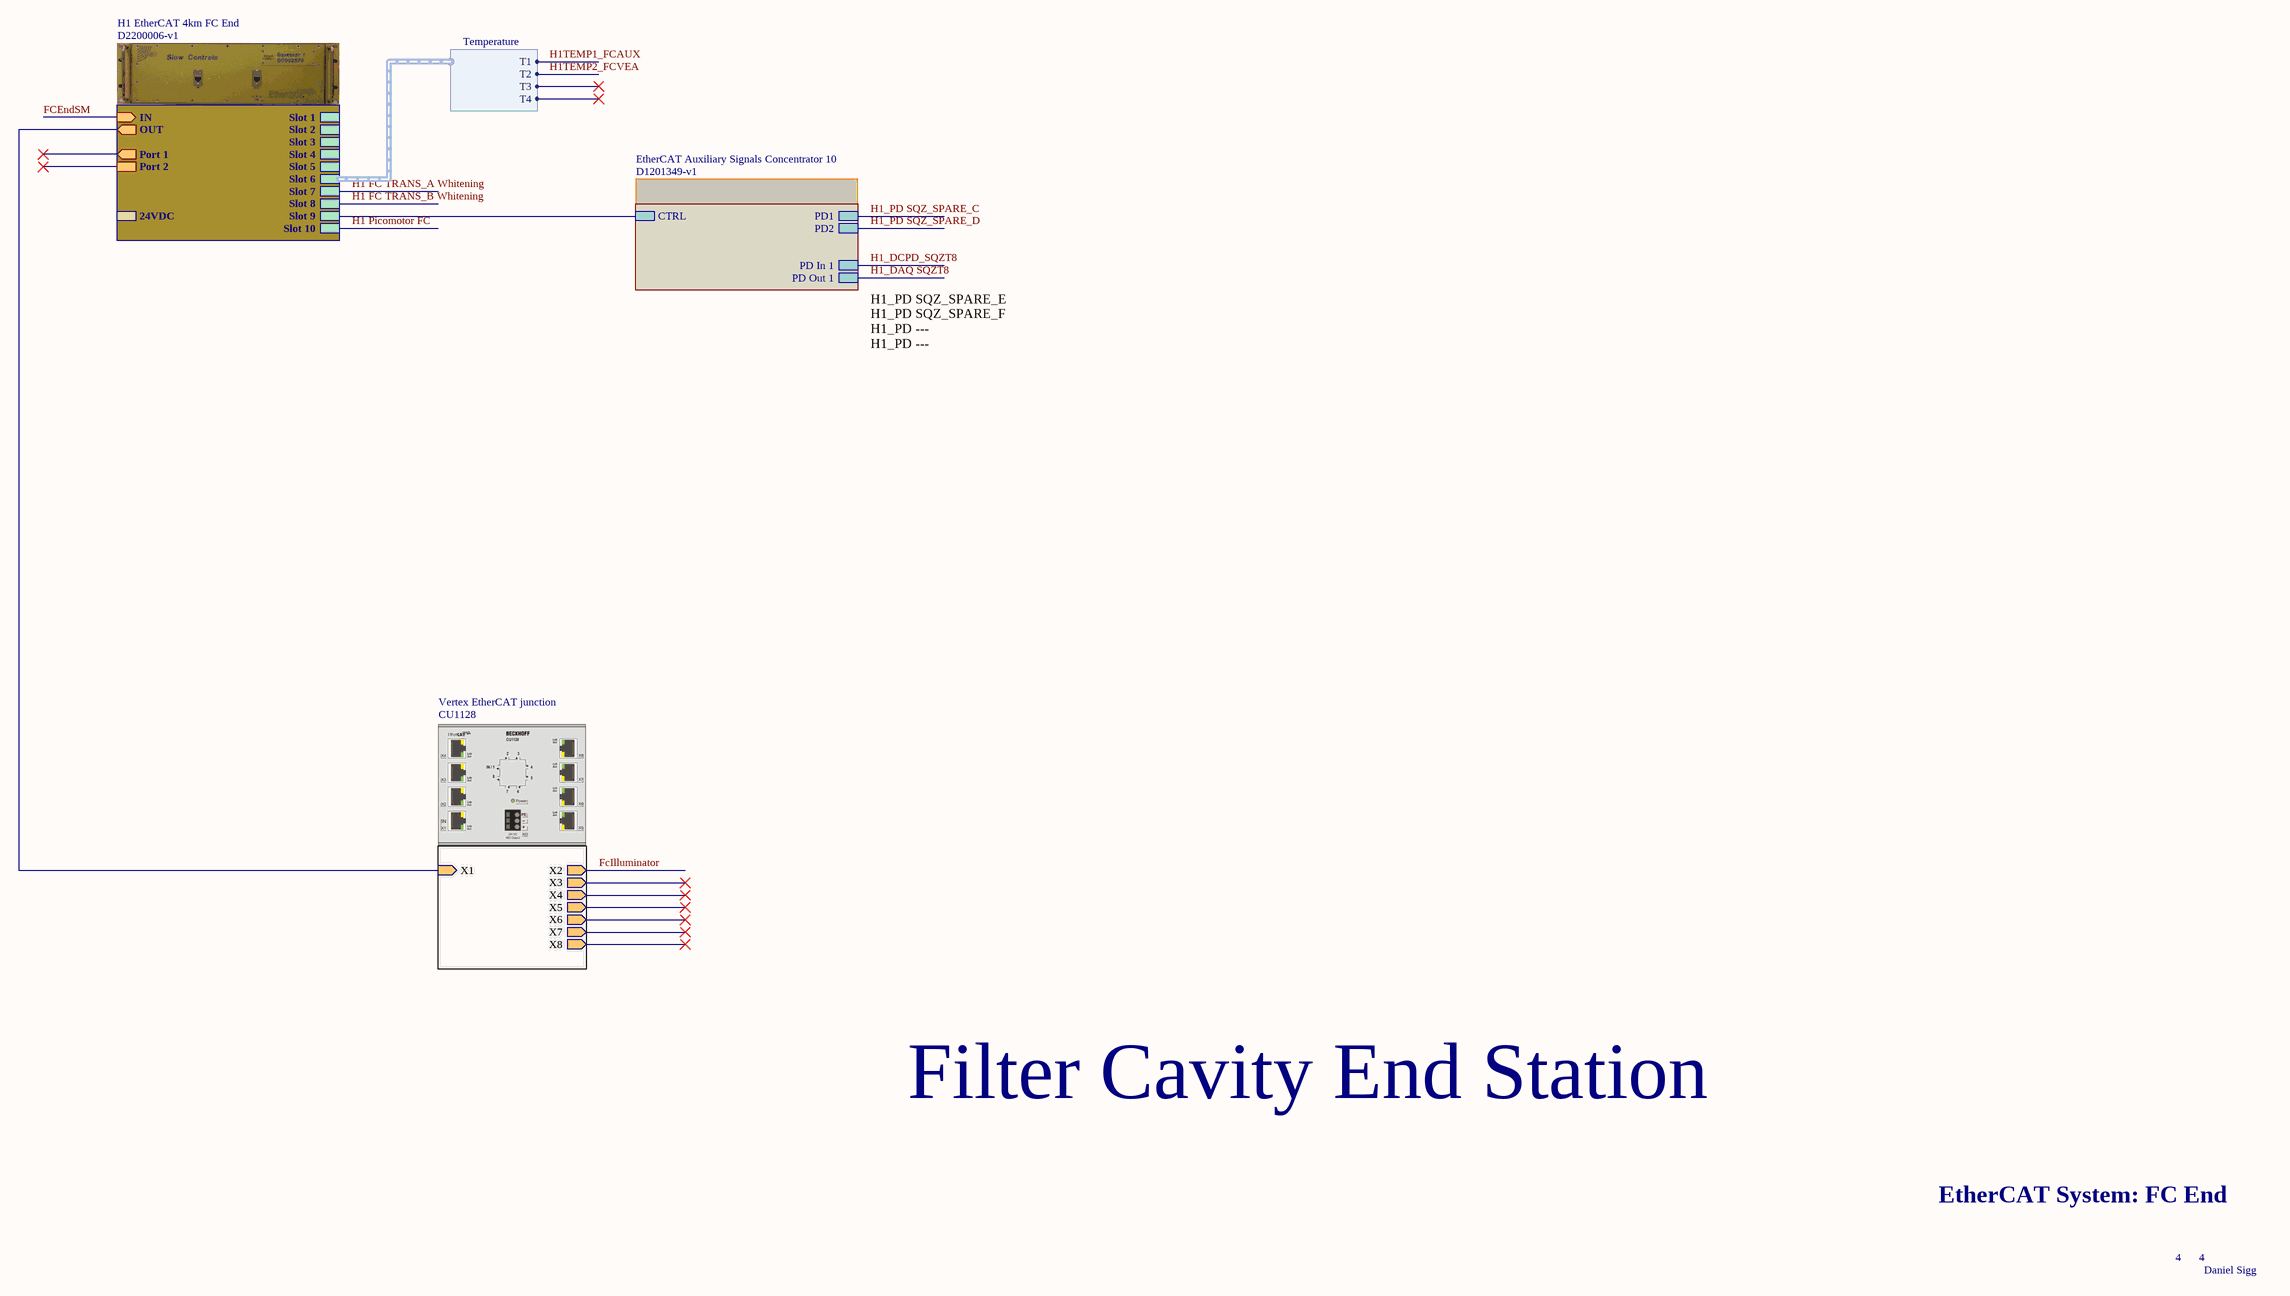
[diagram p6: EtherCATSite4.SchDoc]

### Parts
(Parts that share a designator on the sheet are numbered #1, #2 ... from top to bottom, then left to right.)
H1_EtherCAT_4km_FC_End  Part Number: D2200006-v1  (hidden comment: EtherCAT Chassis)
U15  EtherCAT Auxiliary Signals Concentrator 10  Part Number: D1201349-v1
Vertex_EtherCAT_junction#3  EtherCAT junction  (value not drawn)

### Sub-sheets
EtherCAT4kmCorner = File Name (file not in this document): Slot 1, Slot 2, Slot 3, Slot 4, Slot 5, Slot 6 (harness Temperature), Slot 9, 24VDC, IN (in), OUT (out), Port 1 (out), Port 2, Slot 10, Slot 7, Slot 8
H1 Serial Corner = File Name (file not in this document): X2 (out), X1 (in), X3 (out), X4 (out), X5 (out), X6 (out), X7 (out), X8 (out)
H1 Serial Corner = File Name (file not in this document): CTRL, PD1, PD2, PD In 1, PD Out 1

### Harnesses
Temperature: T1, T2, T3, T4

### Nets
(unnamed): sheet EtherCAT4kmCorner/Slot 9, sheet H1 Serial Corner/CTRL
(unnamed): sheet EtherCAT4kmCorner/OUT, sheet H1 Serial Corner/X1  [a separate net that carries the same name]

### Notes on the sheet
- H1_PD SQZ_SPARE_E
  H1_PD SQZ_SPARE_F
  H1_PD ---
  H1_PD ---
- Filter Cavity End Station
- EtherCAT System: FC End
- 4
- Daniel Sigg

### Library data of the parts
H1_EtherCAT_4km_FC_End = EtherCATchassis
U15 = EtherCATConcentratorAux1: as U1 on sheet EtherCATSite1
Vertex_EtherCAT_junction#3 = CU1128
